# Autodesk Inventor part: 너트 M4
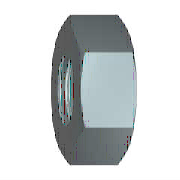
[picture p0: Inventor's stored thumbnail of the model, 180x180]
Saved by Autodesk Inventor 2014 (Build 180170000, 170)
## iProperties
IsCustomPart: 0
Created: 2012-02
Part Number: 너트 M4
Material: 스테인리스강
Description: 6각 너트, 스타일 1 - 제품 등급 A 및 B
Document SubType Name: Modeling
Standard: ISO 4032
Designer: mduedu
Standard Revision: Third edition 1999-08-15
Standards Organization: ISO
Language: ko-KR
Size Designation: M4
Categories: <MemberInstance><Categories><Category DisplayName="조임쇠" InternalName="e4da775c-781d-43d5-af7c-5136215cf5a6" Mnemonic="FSTN"><Category DisplayName="너트" InternalN
Density: 8.08 g/cm^3
Mass: 0.820715 g
Surface Area: 1.59496 cm^2
Volume: 0.101574 cm^3
Appearance: 반광택
Author: mduedu
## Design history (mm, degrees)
sketch "스케치1"
  geometry: L1 (-4.041, 0)-(-2.021, 3.5); L2 (-2.021, 3.5)-(2.021, 3.5); L3 (2.021, 3.5)-(4.041, 0); L4 (4.041, 0)-(2.021, -3.5); L5 (2.021, -3.5)-(-2.021, -3.5); L6 (-2.021, -3.5)-(-4.041, 0); 2 further points
  constraints: 12 end point, 1 coincident, 1 horizontal, 11 other
  dimensions: "d0" = 8.0829 distance of L3.end L1.start (= 1.1547 x SW)
extrude "본체" new body sketch "스케치1" distance "d1" = 3.2 (= KOH); taper "d2" = 0 deg
sketch "스케치2"
  geometry: L1 (0, 2.021)-(0, 4.041) reference; L2 (0, 4.041)-(3.2, 4.041) reference; L3 (3.2, 2.021)-(3.2, 4.041) reference; L4 (-0.64, 0)-(3.84, 0) reference; L5 (0.63, 4.041)-(0, 2.95); L6 (2.57, 4.041)-(3.2, 2.95)
  constraints: 4 end point, 4 point on line
  dimensions: "d3" = 30 deg angle of L1 L5 (= ANG1); "d4" = 30 deg angle of L3 L6 (= ANG2); "d5" = 5.9 diameter of L5.end L4 (= SW0); "d6" = 5.9 diameter of L6.end L4 (= SW01)
revolve "모따기1" sketch "스케치2" stored, may be unused: angle "d7" = 90 deg
sketch "스케치3"
  geometry: 4 further points
  constraints: 1 coincident, 1 other
hole "스레드" sketch "스케치3" at (0, 0) diameter "d25" = 3.242; stored, may be unused: countersink angle "d29" = 82 deg, drill point angle "d31" = 118 deg; dims "d26" = 6, "d27" = 4, "d28" = 2, "d30" = 8
workaxis "Work Axis1"
workplane "Work Plane1"
body "Solid1"
chamfer "모따기2" distance "d8" = 0.37889 (= -0.5 x GD1 + 0.5 x NND); stored, may be unused: angle "d9" = 30 deg, second distance "d40" = 0.37889 (= -0.5 x GD1 + 0.5 x NND)
chamfer "모따기3" distance "d10" = 0.37889 (= -0.5 x GD1 + 0.5 x NND); stored, may be unused: angle "d11" = 30 deg, second distance "d41" = 0.37889 (= -0.5 x GD1 + 0.5 x NND)
other parameters: "ANG1" = 30 deg [user parameter; used in 1 equation term], "ANG2" = 30 deg [user parameter; used in 1 equation term], "NND" = 4 [user parameter; used in 4 equation terms], "KOH" = 3.2 [user parameter; used in 1 equation term], "SW" = 7 [user parameter; used in 2 equation terms], "SW0" = 5.9 [user parameter; used in 2 equation terms], "SW01" = 5.9 (= SW0) [user parameter; used in 1 equation term], "GD1" = 3.24223 (computed from THREADDIA, PTC, TOA) [user parameter; used in 4 equation terms], "d13" = 0, "d14" = 0, "d39" = 0, "d42" = 0, "GUL" = 0.37889 (= 0.541266 x PTC) [user parameter], "TPU" = 14.28571 (computed from PTC) [user parameter], "THREADDIA" = 4 [user parameter; used in 1 equation term], "TOA" = 30 deg [user parameter; used in 1 equation term], "PTC" = 0.7 [user parameter; used in 4 equation terms], "E0" = 8.085 (= 1.155 x SW) [user parameter], "GAL" = 0.37889 (= 0.541266 x PTC) [user parameter]
